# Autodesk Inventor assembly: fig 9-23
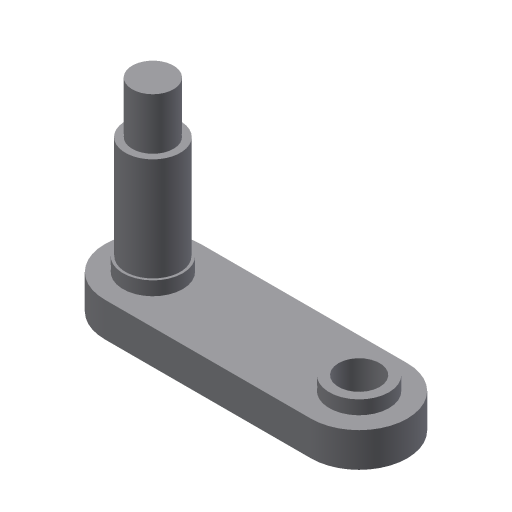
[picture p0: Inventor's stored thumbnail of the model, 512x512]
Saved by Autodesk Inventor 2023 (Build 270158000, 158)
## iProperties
Created: 2002-01
Part Number: fig 9-23
Document SubType Name: Assembly
Designer: ***
Control State: 0
Master: False
Checked Out: False
Shininess: 64.0
Length Units: 11269
Angle Units: 11279
Time Units: 11290
Mass Units: 11283
Length Display Precision: 3
Angle Display Precision: 2
Density: 0.0
Volumn: 0.0
Area: 0.0
PropertySet Name: Model Information
Author: ***
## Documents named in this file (3)
- D:\PROJECTS\Project 2022\Autodesk Inventor For Professional 2023\RESOURCES INVENTOR 2023\RESOURCES INVENTOR 2023\Inventor_2023_Part\Inventor_2023_Part\c09_Inv_2023_prt\fig 9-23.iam
- D:\PROJECTS\Project 2022\Autodesk Inventor For Professional 2023\RESOURCES INVENTOR 2023\RESOURCES INVENTOR 2023\Inventor_2023_Part\Inventor_2023_Part\c09_Inv_2023_prt\Part5.ipt
- D:\PROJECTS\Project 2022\Autodesk Inventor For Professional 2023\RESOURCES INVENTOR 2023\RESOURCES INVENTOR 2023\Inventor_2023_Part\Inventor_2023_Part\c09_Inv_2023_prt\Part6.ipt
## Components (2 placed, 2 different names)
1. Part5:1 — Insert:1
2. Part6:1 — Insert:1
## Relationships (1: Insert 1)
- Insert:1: Part5:1 ↔ Part6:1
